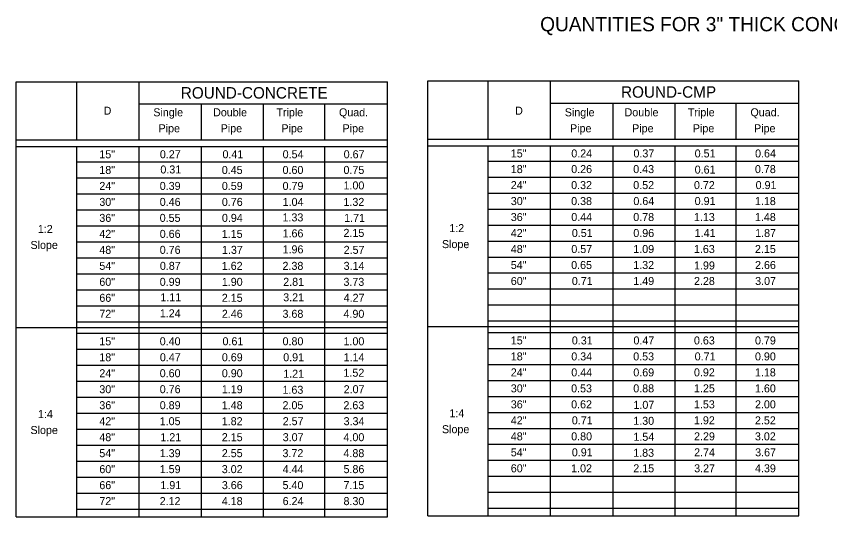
# Model space of a CAD drawing. Extents: x 10064 to 10776, y 10188 to 10407.
# Drawn here: x 10064.4 to 10420.2, y 10187.8 to 10406.7 of the extents above; entities that cross this region are included whole.
import ezdxf

# ---------------------------------------------------------------- set-up
doc = ezdxf.new("R2010")
doc.units = 0
doc.layers.add('Default', color=7, linetype='Continuous')
doc.layers.add('Dimension', color=7, linetype='Continuous')

msp = doc.modelspace()

# ---------------------------------------------------------------- linework, layer by layer
at = {"layer": 'Default'}
for p, q in [((10064.35, 10187.8), (10064.35, 10378.09)), ((10064.35, 10378.09), (10226.73, 10378.09)), ((10090.81, 10352.64), (10090.81, 10378.16)), ((10118.11, 10352.64), (10118.11, 10378.16)), ((10226.73, 10187.8), (10226.73, 10378.09)), ((10244.33, 10188.16), (10244.33, 10378.46)), ((10244.33, 10378.46), (10406.7, 10378.46)), ((10270.78, 10353), (10270.78, 10378.53)), ((10298.08, 10353), (10298.08, 10378.53)), ((10406.7, 10188.16), (10406.7, 10378.46)), ((10118.11, 10368.33), (10226.73, 10368.33)), ((10145.43, 10352.64), (10145.43, 10368.33)), ((10172.53, 10352.64), (10172.53, 10368.33)), ((10199.27, 10352.64), (10199.27, 10368.33)), ((10298.08, 10368.69), (10406.7, 10368.69)), ((10325.4, 10353), (10325.4, 10368.69)), ((10352.5, 10353), (10352.5, 10368.69)), ((10379.25, 10353), (10379.25, 10368.69)), ((10064.35, 10352.64), (10226.73, 10352.64)), ((10244.33, 10353), (10406.7, 10353)), ((10064.35, 10349.71), (10226.73, 10349.71)), ((10090.81, 10187.8), (10090.81, 10349.71)), ((10118.11, 10187.8), (10118.11, 10349.71)), ((10145.43, 10187.8), (10145.43, 10349.71)), ((10172.53, 10187.8), (10172.53, 10349.71)), ((10199.27, 10187.8), (10199.27, 10349.71)), ((10244.33, 10350.08), (10406.7, 10350.08)), ((10270.78, 10188.16), (10270.78, 10350.08)), ((10298.08, 10188.16), (10298.08, 10350.08)), ((10325.4, 10188.16), (10325.4, 10350.08)), ((10352.5, 10188.16), (10352.5, 10350.08)), ((10379.25, 10188.16), (10379.25, 10350.08)), ((10270.78, 10343.35), (10406.7, 10343.35)), ((10090.81, 10342.98), (10226.73, 10342.98)), ((10270.78, 10336.36), (10406.7, 10336.36)), ((10090.81, 10335.99), (10226.73, 10335.99)), ((10270.78, 10329.36), (10406.7, 10329.36)), ((10090.81, 10329), (10226.73, 10329)), ((10090.81, 10322), (10226.73, 10322)), ((10270.78, 10322.37), (10406.7, 10322.37)), ((10090.81, 10315.01), (10226.73, 10315.01)), ((10270.78, 10315.38), (10406.7, 10315.38)), ((10090.81, 10308.02), (10226.73, 10308.02)), ((10270.78, 10308.39), (10406.7, 10308.39)), ((10090.81, 10301.03), (10226.73, 10301.03)), ((10270.78, 10301.4), (10406.7, 10301.4)), ((10090.81, 10294.04), (10226.73, 10294.04)), ((10270.78, 10294.41), (10406.7, 10294.41)), ((10090.81, 10287.05), (10226.73, 10287.05)), ((10270.78, 10287.41), (10406.7, 10287.41)), ((10090.81, 10280.05), (10226.73, 10280.05)), ((10270.78, 10280.42), (10406.7, 10280.42)), ((10090.81, 10273.06), (10226.73, 10273.06)), ((10270.78, 10273.43), (10406.7, 10273.43)), ((10064.35, 10270.63), (10226.73, 10270.63)), ((10244.33, 10271), (10406.7, 10271)), ((10090.81, 10268.04), (10226.73, 10268.04)), ((10270.78, 10268.41), (10406.7, 10268.41)), ((10090.81, 10261.05), (10226.73, 10261.05)), ((10270.78, 10261.42), (10406.7, 10261.42)), ((10270.78, 10254.42), (10406.7, 10254.42)), ((10090.81, 10254.06), (10226.73, 10254.06)), ((10270.78, 10247.43), (10406.7, 10247.43)), ((10090.81, 10247.06), (10226.73, 10247.06)), ((10270.78, 10240.44), (10406.7, 10240.44)), ((10090.81, 10240.07), (10226.73, 10240.07)), ((10090.81, 10233.08), (10226.73, 10233.08)), ((10270.78, 10233.45), (10406.7, 10233.45)), ((10090.81, 10226.09), (10226.73, 10226.09)), ((10270.78, 10226.46), (10406.7, 10226.46)), ((10090.81, 10219.1), (10226.73, 10219.1)), ((10270.78, 10219.47), (10406.7, 10219.47)), ((10090.81, 10212.11), (10226.73, 10212.11)), ((10270.78, 10212.47), (10406.7, 10212.47)), ((10090.81, 10205.11), (10226.73, 10205.11)), ((10270.78, 10205.48), (10406.7, 10205.48)), ((10090.81, 10198.12), (10226.73, 10198.12)), ((10270.78, 10198.49), (10406.7, 10198.49)), ((10090.81, 10191.13), (10226.73, 10191.13)), ((10270.78, 10191.5), (10406.7, 10191.5)), ((10064.35, 10187.8), (10226.73, 10187.8)), ((10244.33, 10188.16), (10406.7, 10188.16))]:
    msp.add_line(p, q, dxfattribs=at)

# ---------------------------------------------------------------- texts
at = {"layer": 'Dimension'}
for s, height, p in [('QUANTITIES FOR 3" THICK CONCRETE SLABS (CY)', 6.25, (10293.5, 10400.12)), ('ROUND-CONCRETE', 5, (10136.31, 10370.71)), ('ROUND-CMP', 5, (10328.87, 10371.08)), ('D', 3.5, (10102.57, 10363.65)), ('Single', 3.5, (10124.3, 10362.95)), ('Double', 3.5, (10150.45, 10362.95)), ('Triple', 3.5, (10178.14, 10362.95)), ('Quad.', 3.5, (10205.51, 10362.95)), ('D', 3.5, (10282.55, 10363.65)), ('Single', 3.5, (10304.28, 10362.95)), ('Double', 3.5, (10330.42, 10362.95)), ('Triple', 3.5, (10358.12, 10362.95)), ('Quad.', 3.5, (10385.48, 10362.95)), ('Pipe', 3.5, (10126.6, 10355.95)), ('Pipe', 3.5, (10153.77, 10355.95)), ('Pipe', 3.5, (10180.33, 10355.95)), ('Pipe', 3.5, (10207.09, 10355.95)), ('Pipe', 3.5, (10306.57, 10355.95)), ('Pipe', 3.5, (10333.74, 10355.95)), ('Pipe', 3.5, (10360.3, 10355.95)), ('Pipe', 3.5, (10387.06, 10355.95)), ('15"', 3.5, (10100.69, 10344.59)), ('0.27', 3.5, (10127.17, 10344.59)), ('0.41', 3.5, (10154.56, 10344.59)), ('0.54', 3.5, (10180.87, 10344.59)), ('0.67', 3.5, (10207.56, 10344.59)), ('15"', 3.5, (10280.66, 10344.96)), ('0.24', 3.5, (10307.12, 10344.96)), ('0.37', 3.5, (10334.31, 10344.96)), ('0.51', 3.5, (10361.09, 10344.96)), ('0.64', 3.5, (10387.51, 10344.96)), ('18"', 3.5, (10100.69, 10337.73)), ('0.31', 3.5, (10127.39, 10337.95)), ('0.45', 3.5, (10154.25, 10337.73)), ('0.60', 3.5, (10180.83, 10337.73)), ('0.75', 3.5, (10207.48, 10337.73)), ('18"', 3.5, (10280.66, 10338.1)), ('0.26', 3.5, (10307.09, 10338.1)), ('0.43', 3.5, (10334.21, 10338.1)), ('0.61', 3.5, (10361.09, 10337.88)), ('0.78', 3.5, (10387.45, 10338.1)), ('24"', 3.5, (10100.69, 10330.74)), ('0.39', 3.5, (10127.11, 10330.74)), ('0.59', 3.5, (10154.28, 10330.74)), ('0.79', 3.5, (10180.84, 10330.74)), ('1.00', 3.5, (10207.49, 10330.96)), ('24"', 3.5, (10280.66, 10331.11)), ('0.32', 3.5, (10307.05, 10331.11)), ('0.52', 3.5, (10334.22, 10331.11)), ('0.72', 3.5, (10360.78, 10331.11)), ('0.91', 3.5, (10387.75, 10331.11)), ('30"', 3.5, (10100.69, 10323.75)), ('0.46', 3.5, (10127.11, 10323.75)), ('0.76', 3.5, (10154.28, 10323.75)), ('1.04', 3.5, (10180.87, 10323.75)), ('1.32', 3.5, (10207.47, 10323.75)), ('30"', 3.5, (10280.66, 10324.12)), ('0.38', 3.5, (10307.06, 10324.12)), ('0.64', 3.5, (10334.28, 10324.12)), ('0.91', 3.5, (10361.09, 10324.14)), ('1.18', 3.5, (10387.45, 10324.12)), ('36"', 3.5, (10100.69, 10316.76)), ('0.55', 3.5, (10127.09, 10316.76)), ('0.94', 3.5, (10154.31, 10316.76)), ('1.33', 3.5, (10180.8, 10316.97)), ('1.71', 3.5, (10207.78, 10316.76)), ('36"', 3.5, (10280.66, 10317.13)), ('0.44', 3.5, (10307.12, 10317.13)), ('0.78', 3.5, (10334.23, 10317.13)), ('1.13', 3.5, (10360.77, 10317.13)), ('1.48', 3.5, (10387.45, 10317.13)), ('1:2', 3.5, (10073.79, 10311.92)), ('1:2', 3.5, (10253.76, 10312.29)), ('42"', 3.5, (10100.69, 10309.77)), ('0.66', 3.5, (10127.11, 10309.77)), ('1.15', 3.5, (10154.25, 10309.77)), ('1.66', 3.5, (10180.84, 10309.98)), ('2.15', 3.5, (10207.48, 10310.2)), ('42"', 3.5, (10280.66, 10310.14)), ('0.51', 3.5, (10307.36, 10310.14)), ('0.96', 3.5, (10334.25, 10310.14)), ('1.41', 3.5, (10361.09, 10310.14)), ('1.87', 3.5, (10387.54, 10310.14)), ('Slope', 3.5, (10070.58, 10304.92)), ('Slope', 3.5, (10250.55, 10305.29)), ('48"', 3.5, (10100.69, 10302.78)), ('0.76', 3.5, (10127.11, 10302.78)), ('1.37', 3.5, (10154.34, 10302.78)), ('1.96', 3.5, (10180.84, 10302.99)), ('2.57', 3.5, (10207.56, 10302.78)), ('48"', 3.5, (10280.66, 10303.14)), ('0.57', 3.5, (10307.14, 10303.14)), ('1.09', 3.5, (10334.25, 10303.14)), ('1.63', 3.5, (10360.77, 10303.14)), ('2.15', 3.5, (10387.45, 10303.14)), ('54"', 3.5, (10100.69, 10295.78)), ('0.87', 3.5, (10127.17, 10295.78)), ('1.62', 3.5, (10154.24, 10295.78)), ('2.38', 3.5, (10180.81, 10295.78)), ('3.14', 3.5, (10207.54, 10295.78)), ('54"', 3.5, (10280.66, 10296.15)), ('0.65', 3.5, (10307.06, 10296.15)), ('1.32', 3.5, (10334.22, 10296.15)), ('1.99', 3.5, (10360.81, 10295.95)), ('2.66', 3.5, (10387.48, 10296.15)), ('60"', 3.5, (10100.69, 10288.79)), ('0.99', 3.5, (10127.11, 10288.79)), ('1.90', 3.5, (10154.27, 10288.79)), ('2.81', 3.5, (10181.12, 10288.79)), ('3.73', 3.5, (10207.46, 10288.79)), ('60"', 3.5, (10280.66, 10289.16)), ('0.71', 3.5, (10307.36, 10289.16)), ('1.49', 3.5, (10334.25, 10289.16)), ('2.28', 3.5, (10360.79, 10289.16)), ('3.07', 3.5, (10387.54, 10289.16)), ('66"', 3.5, (10100.69, 10281.8)), ('1.11', 3.5, (10127.39, 10282.02)), ('2.15', 3.5, (10154.26, 10281.8)), ('3.21', 3.5, (10181.12, 10282.02)), ('4.27', 3.5, (10207.56, 10281.8)), ('72"', 3.5, (10100.69, 10274.81)), ('1.24', 3.5, (10127.14, 10275.02)), ('2.46', 3.5, (10154.28, 10274.81)), ('3.68', 3.5, (10180.81, 10274.81)), ('4.90', 3.5, (10207.49, 10274.81)), ('15"', 3.5, (10100.69, 10262.79)), ('0.40', 3.5, (10127.1, 10262.79)), ('0.61', 3.5, (10154.56, 10262.79)), ('0.80', 3.5, (10180.83, 10262.79)), ('1.00', 3.5, (10207.49, 10262.79)), ('15"', 3.5, (10280.66, 10263.16)), ('0.31', 3.5, (10307.36, 10263.16)), ('0.47', 3.5, (10334.31, 10263.16)), ('0.63', 3.5, (10360.77, 10263.16)), ('0.79', 3.5, (10387.48, 10263.16)), ('18"', 3.5, (10100.69, 10255.8)), ('0.47', 3.5, (10127.17, 10255.8)), ('0.69', 3.5, (10154.28, 10255.8)), ('0.91', 3.5, (10181.12, 10255.8)), ('1.14', 3.5, (10207.53, 10255.8)), ('18"', 3.5, (10280.66, 10256.17)), ('0.34', 3.5, (10307.12, 10256.17)), ('0.53', 3.5, (10334.21, 10256.17)), ('0.71', 3.5, (10361.09, 10256.17)), ('0.90', 3.5, (10387.47, 10256.17)), ('24"', 3.5, (10100.69, 10248.81)), ('0.60', 3.5, (10127.1, 10248.81)), ('0.90', 3.5, (10154.27, 10248.81)), ('1.21', 3.5, (10181.12, 10248.59)), ('1.52', 3.5, (10207.47, 10249.03)), ('24"', 3.5, (10280.66, 10249.18)), ('0.44', 3.5, (10307.12, 10249.18)), ('0.69', 3.5, (10334.25, 10249.18)), ('0.92', 3.5, (10360.78, 10249.2)), ('1.18', 3.5, (10387.45, 10249.18)), ('30"', 3.5, (10100.69, 10241.82)), ('0.76', 3.5, (10127.11, 10241.82)), ('1.19', 3.5, (10154.28, 10241.82)), ('1.63', 3.5, (10180.8, 10241.58)), ('2.07', 3.5, (10207.56, 10241.82)), ('30"', 3.5, (10280.66, 10242.19)), ('0.53', 3.5, (10307.05, 10242.19)), ('0.88', 3.5, (10334.23, 10242.19)), ('1.25', 3.5, (10360.79, 10242.21)), ('1.60', 3.5, (10387.47, 10242.19)), ('36"', 3.5, (10100.69, 10234.83)), ('0.89', 3.5, (10127.11, 10234.83)), ('1.48', 3.5, (10154.25, 10234.83)), ('2.05', 3.5, (10180.82, 10234.83)), ('2.63', 3.5, (10207.46, 10234.83)), ('36"', 3.5, (10280.66, 10235.2)), ('0.62', 3.5, (10307.05, 10235.2)), ('1.07', 3.5, (10334.31, 10234.99)), ('1.53', 3.5, (10360.77, 10235.2)), ('2.00', 3.5, (10387.47, 10235.2)), ('1:4', 3.5, (10073.85, 10230.96)), ('1:4', 3.5, (10253.83, 10231.33)), ('42"', 3.5, (10100.69, 10227.84)), ('1.05', 3.5, (10127.09, 10227.84)), ('1.82', 3.5, (10154.24, 10227.84)), ('2.57', 3.5, (10180.9, 10227.84)), ('3.34', 3.5, (10207.54, 10227.84)), ('42"', 3.5, (10280.66, 10228.2)), ('0.71', 3.5, (10307.36, 10228.2)), ('1.30', 3.5, (10334.24, 10228)), ('1.92', 3.5, (10360.78, 10228.23)), ('2.52', 3.5, (10387.44, 10228.2)), ('Slope', 3.5, (10070.58, 10223.96)), ('Slope', 3.5, (10250.55, 10224.33)), ('48"', 3.5, (10100.69, 10220.84)), ('1.21', 3.5, (10127.39, 10220.84)), ('2.15', 3.5, (10154.26, 10220.84)), ('3.07', 3.5, (10180.9, 10220.84)), ('4.00', 3.5, (10207.49, 10220.84)), ('48"', 3.5, (10280.66, 10221.21)), ('0.80', 3.5, (10307.08, 10221.21)), ('1.54', 3.5, (10334.29, 10221.01)), ('2.29', 3.5, (10360.82, 10221.21)), ('3.02', 3.5, (10387.44, 10221.21)), ('54"', 3.5, (10100.69, 10213.85)), ('1.39', 3.5, (10127.11, 10213.85)), ('2.55', 3.5, (10154.26, 10213.85)), ('3.72', 3.5, (10180.8, 10213.85)), ('4.88', 3.5, (10207.48, 10213.85)), ('54"', 3.5, (10280.66, 10214.22)), ('0.91', 3.5, (10307.36, 10214.22)), ('1.83', 3.5, (10334.21, 10214.02)), ('2.74', 3.5, (10360.85, 10214.22)), ('3.67', 3.5, (10387.54, 10214.22)), ('60"', 3.5, (10100.69, 10206.86)), ('1.59', 3.5, (10127.11, 10206.86)), ('3.02', 3.5, (10154.24, 10206.86)), ('4.44', 3.5, (10180.87, 10206.86)), ('5.86', 3.5, (10207.5, 10206.86)), ('60"', 3.5, (10280.66, 10207.23)), ('1.02', 3.5, (10307.05, 10207.23)), ('2.15', 3.5, (10334.23, 10207.23)), ('3.27', 3.5, (10360.87, 10207.23)), ('4.39', 3.5, (10387.48, 10207.23)), ('66"', 3.5, (10100.69, 10199.87)), ('1.91', 3.5, (10127.39, 10199.87)), ('3.66', 3.5, (10154.28, 10199.87)), ('5.40', 3.5, (10180.83, 10199.87)), ('7.15', 3.5, (10207.48, 10199.87)), ('72"', 3.5, (10100.69, 10192.88)), ('2.12', 3.5, (10127.07, 10192.88)), ('4.18', 3.5, (10154.25, 10192.88)), ('6.24', 3.5, (10180.87, 10192.88)), ('8.30', 3.5, (10207.49, 10192.88))]:
    msp.add_text(s, height=height, dxfattribs=at).set_placement(p)

doc.saveas('drawing.dxf')
